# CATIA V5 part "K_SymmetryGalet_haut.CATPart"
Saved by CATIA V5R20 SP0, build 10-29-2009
Part number: Symmetry of Galet_haut
Bounding box of the stored display mesh (mm): x 0 to 17.955, y -11.571 to 11.571, z -11.571 to 11.571
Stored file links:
  G:\Khaled_CFAO_2011\SIL\SIL_GR2\zthiebault\Khaled\CAD_ThinkMOTION\K_SymmetryGalet_haut.CATPart
  G:\Khaled_CFAO_2011\SIL\SIL_GR2\zthiebault\Khaled\CAD_ThinkMOTION\K_Galet_haut2.CATPart
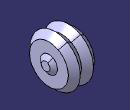
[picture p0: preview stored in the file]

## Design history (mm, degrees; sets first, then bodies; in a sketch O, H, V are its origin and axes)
Body1 (main body)
  Body2 "Corps du corps principal d'origine"
    Solid1: linked copy from another document
  Assemble1: tool Body2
